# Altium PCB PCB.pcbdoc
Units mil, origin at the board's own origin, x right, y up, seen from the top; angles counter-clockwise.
Board outline 1334.95 x 2050.7 mil, 2 copper layers (Top Layer, Bottom Layer); 18 components, 22 nets, 95 pads, 86 vias.
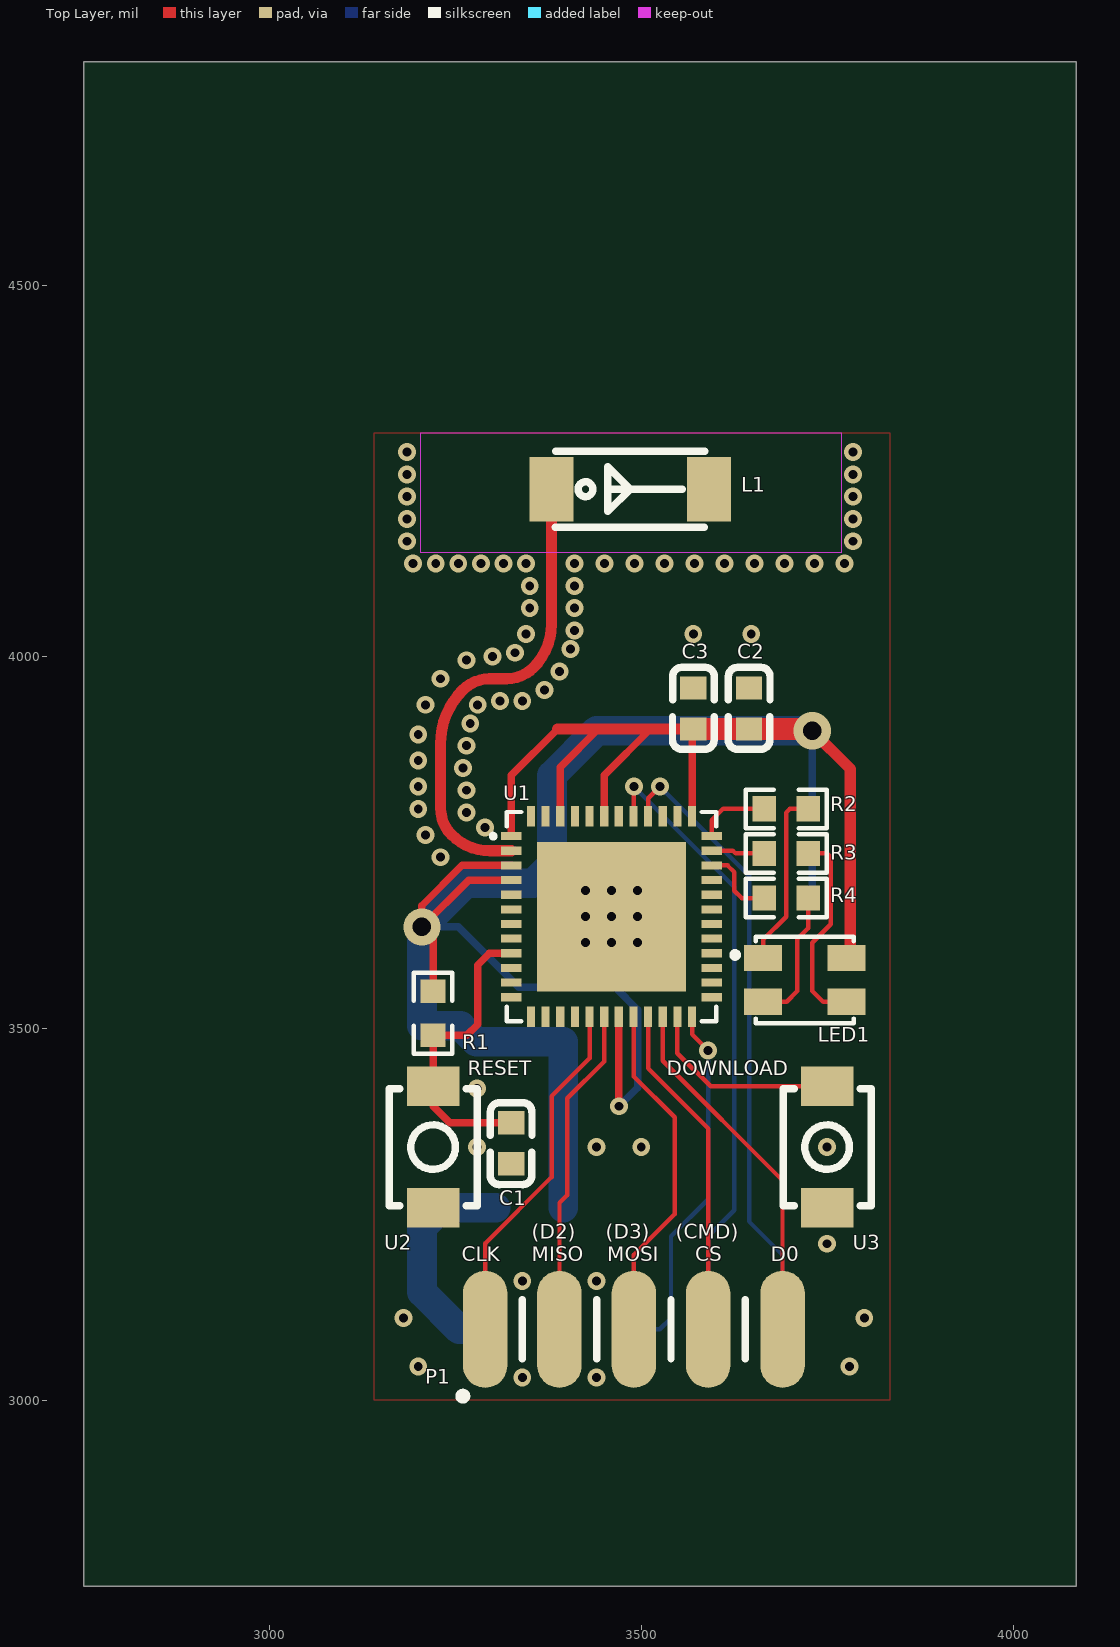
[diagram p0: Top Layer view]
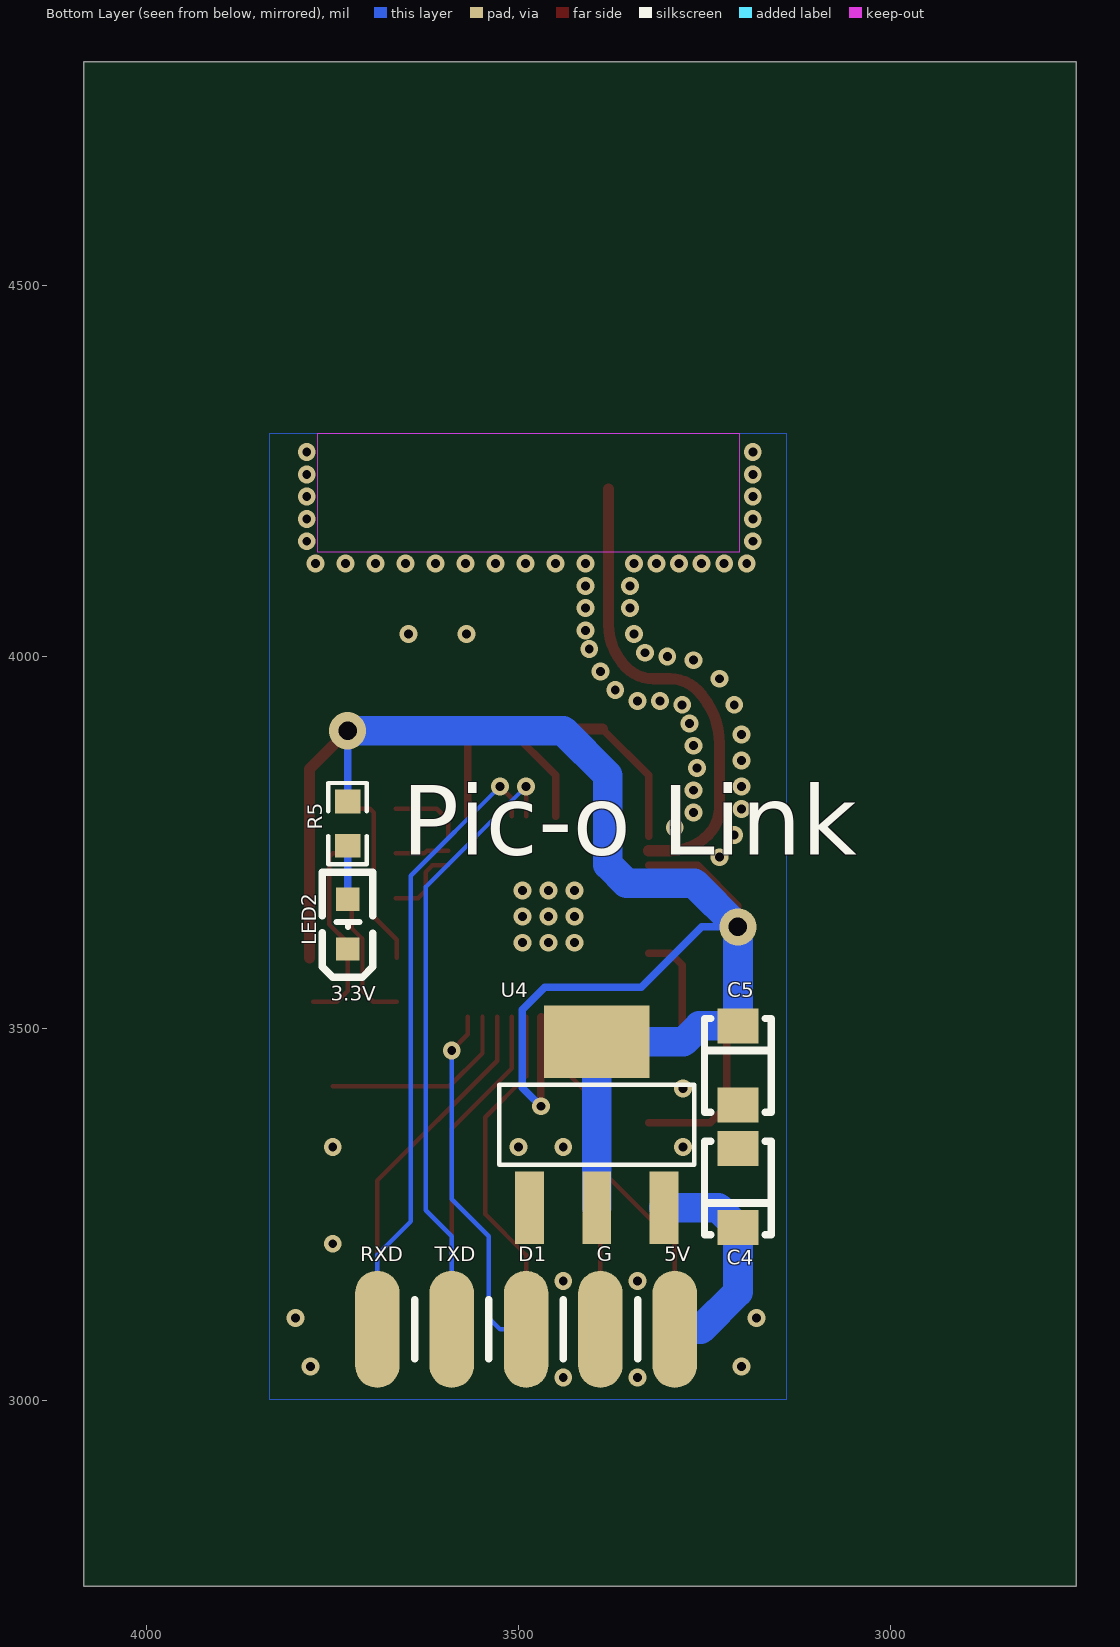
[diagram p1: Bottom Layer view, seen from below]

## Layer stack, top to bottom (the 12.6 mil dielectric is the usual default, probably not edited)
Top Solder: solder mask 0.4, Solder Resist, Dk 3.5
Top Layer: signal copper 1.4
Dielectric 1: dielectric 12.6, FR-4, Dk 4.8
Bottom Layer: signal copper 1.4
Bottom Solder: solder mask 0.4, Solder Resist, Dk 3.5

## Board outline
4084.95,2750 2750,2750 2750,4800.7 4084.95,4800.7

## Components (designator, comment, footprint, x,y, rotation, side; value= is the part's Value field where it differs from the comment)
C1 "" C0603_1 3324.95,3345.7 r90 top
C2 "" C0603_1 3644.95,3930.7 r270 top
C3 "" C0603_1 3569.95,3930.7 r270 top
C4 "" CAP-SMD_L3.2-W1.6 3204.95,3285.7 r90 bottom
C5 "" CAP-SMD_L3.2-W1.6 3204.95,3450.7 r270 bottom
L1 "" ANT2051_1 3484.95,4225.7 r0 top
LED1 "" LED-SMD_4P-L3.2-W2.7-TL_HL-AF-3528S39FU70GH20_1 3719.95,3565.7 r180 top
LED2 "" LED0603-R-RD 3729.95,3640.7 r90 bottom
P1 "" "2*5 双面 排针_2" 3489.95,3095.7 r90 top
R1 "" R0603_1 3219.95,3520.7 r90 top
R2 "" R0603_1 3694.95,3795.7 r180 top
R3 "" R0603_1 3694.95,3735.7 r180 top
R4 "" R0603_1 3694.95,3675.7 r180 top
R5 "" R0603_1 3729.95,3776 r90 bottom
U1 "" QFN-48_L7.0-W7.0-P0.50-BL-EP5.1 3459.95,3650.7 r270 top
U2 "" SW-SMD_L4.0-W3.0-LS4.8-1 3219.95,3340.7 r90 top
U3 "" SW-SMD_L4.0-W3.0-LS4.8-1 3749.95,3340.7 r90 top
U4 "" SOT-223-4_L6.5-W3.5-P2.30-LS7.0-BR_1 3394.95,3370.7 r270 bottom

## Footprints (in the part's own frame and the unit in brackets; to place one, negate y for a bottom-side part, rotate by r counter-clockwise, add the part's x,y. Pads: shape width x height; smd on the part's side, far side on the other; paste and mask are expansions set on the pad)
"2*5 双面 排针_2" [mm]
  oval 4x1.52 smd: 1(0,5.08) 3(0,2.54) 5(0,0) 7(0,-2.54) 9(0,-5.08)
  oval 4x1.52 smd far side: 2(0,5.08) 4(0,2.54) 6(0,0) 8(0,-2.54) 10(0,-5.08)
  silkscreen extent -2.41,-3.81 1.02,5.97
ANT2051_1 [mil]
  rect 59.1x86.6 smd: 1(-105.9,0) 2(105.9,0)
  silkscreen extent -101,-51 100,51
C0603_1 [mil]
  rect 31.5x35.4 smd: 1(-27.6,0) 2(27.6,0)
  silkscreen extent -55,-28 55,28
CAP-SMD_L3.2-W1.6 [mil]
  rect 47.2x55.1 smd: 1(-53.1,0) 2(53.2,0)
  silkscreen extent -63,-45 63,45
LED0603-R-RD [mm]
  rect 0.8x0.8 smd: 1(0.851,0) 2(-0.851,0)
  silkscreen extent -1.82,-0.86 1.77,0.86
LED-SMD_4P-L3.2-W2.7-TL_HL-AF-3528S39FU70GH20_1 [mil]
  rect 51.4x35.4 smd: 1(56.2,-29.5) 2(-56.2,-29.5) 3(-56.2,29.5) 4(56.2,29.5)
  Mid-Layer 2 circle w2.4: c-47.3,-55.1 r1.2
  silkscreen extent -66,-58 98,58
QFN-48_L7.0-W7.0-P0.50-BL-EP5.1 [mil]
  rect 11x27.6 smd: 1(-108.3,-134.9) 2(-88.6,-134.9) 3(-68.9,-134.9) 4(-49.2,-134.9) 5(-29.5,-134.9) 6(-9.8,-134.9) 7(9.8,-134.9) 8(29.5,-134.9) 9(49.2,-134.9) 10(68.9,-134.9) 11(88.6,-134.9) 12(108.3,-134.9) 25(108.3,134.9) 26(88.6,134.9) 27(68.9,134.9) 28(49.2,134.9) 29(29.5,134.9) 30(9.8,134.9) 31(-9.8,134.9) 32(-29.5,134.9) 33(-49.2,134.9) 34(-68.9,134.9) 35(-88.6,134.9) 36(-108.3,134.9)
  rect 27.6x11 smd: 13(134.9,-108.3) 14(134.9,-88.6) 15(134.9,-68.9) 16(134.9,-49.2) 17(134.9,-29.5) 18(134.9,-9.8) 19(134.9,9.8) 20(134.9,29.5) 21(134.9,49.2) 22(134.9,68.9) 23(134.9,88.6) 24(134.9,108.3) 37(-134.9,108.3) 38(-134.9,88.6) 39(-134.9,68.9) 40(-134.9,49.2) 41(-134.9,29.5) 42(-134.9,9.8) 43(-134.9,-9.8) 44(-134.9,-29.5) 45(-134.9,-49.2) 46(-134.9,-68.9) 47(-134.9,-88.6) 48(-134.9,-108.3)
  rect 200.8x200.8 smd: 49(0,0)
  silkscreen extent -141,-162 141,141
R0603_1 [mil]
  rect 31.8x34 smd: 1(-29.7,0) 2(29.7,0)
  silkscreen extent -54,-26 54,26
SOT-223-4_L6.5-W3.5-P2.30-LS7.0-BR_1 [mil]
  rect 97.2x38.6 smd: 1(111.6,-90.5) 2(111.6,0) 3(111.6,90.6)
  rect 97.2x141.7 smd: 4(-111.6,0)
  silkscreen extent -54,-131 54,131
SW-SMD_L4.0-W3.0-LS4.8-1 [mil]
  rect 53.2x70.9 smd: 1(-81.7,0) 2(81.7,0)
  silkscreen extent -79,-59 79,59

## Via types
v1: diameter 24.02, hole 12.01, Top Layer to Bottom Layer, 54 vias
v2: diameter 24, hole 12, Top Layer to Bottom Layer, 30 vias
v3: diameter 50, hole 25, Top Layer to Bottom Layer, 2 vias

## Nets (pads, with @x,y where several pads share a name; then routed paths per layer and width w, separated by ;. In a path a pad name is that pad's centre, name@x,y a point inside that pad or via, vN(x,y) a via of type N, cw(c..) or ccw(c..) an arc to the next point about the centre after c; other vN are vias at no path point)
$1N205: L1.1 U1.2 | length 642.3
  Top Layer w15: U1.2 3296.61,3739.3 cw(c3296.61,3812.36) 3244.95,3760.7 cw(c3281.16,3796.91) 3229.95,3796.91 3229.95,3883.27 cw(c3332.38,3883.27) 3259.95,3955.7 cw(c3296.16,3919.49) 3296.16,3970.7 3318.74,3970.7 ccw(c3318.74,4021.91) 3354.95,3985.7 ccw(c3296.77,4043.88) 3379.05,4043.88 L1.1
$1N302: LED1.1 R2.1 | length 240.2
  Top Layer w6: LED1.1 3663.75,3619.5 3694.95,3650.7 3694.95,3790.7 3699.95,3795.7 R2.1
$1N303: LED1.3 R3.1 | length 274.9
  Top Layer w6: R3.1 3749.95,3735.7 3754.95,3730.7 3754.95,3640.7 3729.95,3615.7 3729.95,3550.7 3744.45,3536.2 LED1.3
$1N304: LED1.4 R4.1 | length 183.3
  Top Layer w6: LED1.4 3695.45,3536.2 3709.95,3550.7 3709.95,3620.7 3724.65,3635.4 R4.1
$1N6027: U1.23 U3.2 | length 268.6
  Top Layer w6: U1.23 3548.55,3467.1 3593.25,3422.4 U3.2
$1N9569: LED2.1 R5.1 | length 72.1
  Bottom Layer w10: LED2.1 R5.1
B: R3.2 U1.35 | length 71.9
  Top Layer w6: U1.35 3623.24,3739.3 3626.84,3735.7 R3.2
CLK: P1.1 U1.17 | length 478.3
  Top Layer w6: P1.1 3289.95,3211.16 3379.24,3300.45 3379.24,3409.14 3430.45,3460.34 U1.17
CS: P1.7 U1.21 | length 453.6
  Top Layer w6: U1.21 3509.15,3446.5 3589.95,3365.7 P1.7
EN: C1.2 R1.1 U1.9 U2.2 | length 407.3
  Top Layer w10: C1.2 3242.35,3373.3 3219.95,3395.7 U2.2 R1.1 3265.25,3491 3279.95,3505.7 3279.95,3585.7 3295.75,3601.5 U1.9
G: R4.2 U1.34 | length 103.2
  Top Layer w6: U1.34 3616.05,3719.6 3624.95,3710.7 3624.95,3685.7 3634.95,3675.7 R4.2
GND: C1.1 C2.1 C3.1 C4.2 C5.2 LED2.2 P1.4 U1.49 U2.1 U3.1 U4.1
  other v1: 3199.95,3045.7 3779.95,3045.7 3179.95,3110.7 3799.95,3110.7 3749.95,3210.7 3279.05,3340.7 3439.95,3340.7 3499.95,3340.7 3749.95,3340.7 3279.05,3419.4 3424.95,3615.7 3459.95,3615.7 3494.95,3615.7 3424.95,3650.7 3459.95,3650.7 3494.95,3650.7 3424.95,3685.7 3459.95,3685.7 3494.95,3685.7 3229.95,3730.7 3209.95,3760.7 3289.95,3770.7 3264.95,3790.7 3199.95,3795.7 3264.95,3820.7 3199.95,3825.7 3259.95,3850.7 3199.95,3860.7 3264.95,3880.7 3199.95,3895.7 3269.95,3910.7 3209.95,3935.7 3279.95,3935.7 3309.95,3940.7 3339.95,3940.7 3369.95,3955.7 3229.95,3970.7 3389.95,3980.7 3264.95,3995.7 3299.95,4000.7 3329.95,4005.7 3404.95,4010.7 3344.95,4030.7 3569.95,4030.7 3647.88,4030.7 3409.95,4035.7 3349.95,4065.7 3409.95,4065.7 3349.95,4095.7 3409.95,4095.7
  other v2: 3339.95,3030.81 3439.95,3030.81 3339.95,3160.7 3439.95,3160.7 3193.1,4125.7 3223.47,4125.7 3253.84,4125.7 3284.21,4125.7 3314.58,4125.7 3344.95,4125.7 3409.95,4125.7 3450.32,4125.7 3490.68,4125.7 3531.05,4125.7 3571.42,4125.7 3611.78,4125.7 3652.15,4125.7 3692.51,4125.7 3732.88,4125.7 3773.25,4125.7 3184.95,4155.7 3784.95,4155.7 3184.95,4185.7 3784.95,4185.7 3184.95,4215.7 3784.95,4215.7 3184.95,4245.7 3784.95,4245.7 3184.95,4275.7 3784.95,4275.7
HS2_DATA0: P1.9 U1.22 | length 486.8
  Top Layer w6: U1.22 3528.85,3456.8 3689.95,3295.7 P1.9
HS2_DATA1: P1.6 U1.24 | length 491
  Top Layer w6: U1.24 3568.25,3492.4 v1(3589.95,3470.7)
  Bottom Layer w6: P1.6 3524.95,3095.7 3539.95,3110.7 3539.95,3220.7 3589.95,3270.7 v1(3589.95,3470.7)
MISO: P1.3 U1.18 | length 445
  Top Layer w6: P1.3 3389.95,3265.7 3400.5,3276.25 3400.5,3406.25 3450.15,3455.9 U1.18
MOSI: P1.5 U1.20 | length 465.9
  Top Layer w6: U1.20 3489.95,3515.3 3489.95,3435.7 3544.95,3380.7 3544.95,3250.7 3489.95,3195.7 P1.5
R: R2.2 U1.36 | length 98.3
  Top Layer w6: U1.36 3594.85,3780.6 3609.95,3795.7 R2.2
U0RXD: P1.10 U1.40 | length 845
  Top Layer w6: U1.40 3509.15,3809.9 v1(3524.95,3825.7)
  Bottom Layer w6: v1(3524.95,3825.7) 3644.95,3705.7 3644.95,3240.7 3689.95,3195.7 P1.10
U0TXD: P1.8 U1.41 | length 840.7
  Top Layer w6: U1.41 3489.95,3786.1 v1(3489.95,3825.7)
  Bottom Layer w6: v1(3489.95,3825.7) 3624.95,3690.7 3624.95,3255.7 3589.95,3220.7 P1.8
VCC_3V3: C2.2 C3.2 C5.1 LED1.2 R1.2 R5.2 U1.1 U1.3 U1.4 U1.19 U1.37 U1.43 U1.46 U4.2 U4.4 | length 3602
  Top Layer w10: R1.2 3219.95,3621.97 v3(3204.95,3636.97) ; U1.4 3267.88,3699.9 v3(3204.95,3636.97) ; U1.3 3258.85,3719.6 3204.95,3665.7 v3(3204.95,3636.97) ; U1.1 3325.05,3840.8 3387.35,3903.1 ; U1.46 3391.05,3851.8 3442.35,3903.1 ; U1.43 3450.15,3840.9 3512.35,3903.1 ; U1.19 3469.95,3515.6 v1(3469.95,3395.7) ; U1.37 3568.25,3901.4 C3.2
  Top Layer w15: 3387.35,3903.1 3442.35,3903.1 3512.35,3903.1 C3.2 ; v3(3729.95,3900.7) 3781.15,3849.5 LED1.2@3781.15,3595.2
  Top Layer w30: C3.2 C2.2 3727.55,3903.1 v3(3729.95,3900.7)
  Bottom Layer w10: v3(3204.95,3636.97) 3253.68,3636.97 3334.95,3555.7 3464.95,3555.7 3494.95,3525.7 3494.95,3420.7 v1(3469.95,3395.7) ; R5.2 v3(3729.95,3900.7)
  Bottom Layer w40: U4.2 U4.4 3278.35,3482.3 3256.85,3503.8 C5.1 v3(3204.95,3636.97) 3263.68,3695.7 3354.95,3695.7 3379.95,3720.7 3379.95,3840.7 3439.95,3900.7 v3(3729.95,3900.7)
VCC_5V: C4.1 P1.2 U4.3 | length 303
  Bottom Layer w40: P1.2 3254.95,3095.7 3204.95,3145.7 C4.1 3231.45,3259.1 U4.3
"": L1.2 U1.5 U1.6 U1.7 U1.8 U1.10 U1.11 U1.12 U1.13 U1.14 U1.15 U1.16 U1.25 U1.26 U1.27 U1.28 U1.29 U1.30 U1.31 U1.32 U1.33 U1.38 U1.39 U1.42 U1.44 U1.45 U1.47 U1.48

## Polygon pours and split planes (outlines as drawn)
GND on Top Layer (solid, remove dead copper, pour order 0): 3139.95,3000.7 3834.95,3000.7 3834.95,4300.7 3139.95,4300.7
GND on Bottom Layer (solid, remove dead copper, pour order 1): 3139.95,3000.7 3834.95,3000.7 3834.95,4300.7 3139.95,4300.7

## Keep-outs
Top Layer:
  region net "": 3202.95,4140.7 3769.95,4140.7 3769.95,4300.7 3202.95,4300.7
Bottom Layer:
  region net "": 3202.95,4140.7 3769.95,4140.7 3769.95,4300.7 3202.95,4300.7

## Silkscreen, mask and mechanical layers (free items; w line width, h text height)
Top Overlay:
  text "RESET" at 3266.58,3437.36 h19.47
  text "DOWNLOAD" at 3534.01,3437.36 h19.47
  text "(D2)" at 3352.43,3217.28 h19.47
  text "(D3)" at 3452.43,3217.28 h19.47
  text "(CMD)" at 3546.58,3217.28 h19.47
  text "CLK" at 3258.29,3187.36 h19.47
  text "MISO" at 3352.88,3187.36 h19.47
  text "MOSI" at 3454.33,3187.36 h19.47
  text "CS" at 3572.29,3187.36 h19.47
  text "D0" at 3674.14,3187.36 h19.47
Bottom Overlay:
  text "Pic-o Link" at 3656.86,3733.86 h93.59
  text "3.3V" at 3752.43,3537.36 h19.47
  text "5V" at 3304.14,3187.36 h19.47
  text "G" at 3395.2,3187.29 h19.61
  text "D1" at 3500.24,3187.36 h19.47
  text "TXD" at 3612.99,3187.36 h19.47
  text "RXD" at 3713.29,3187.36 h19.47
Top Solder:
  region net "": 3202.95,4140.7 3769.95,4140.7 3769.95,4300.7 3202.95,4300.7
Bottom Solder:
  region net "": 3202.95,4140.7 3769.95,4140.7 3769.95,4300.7 3202.95,4300.7
Mechanical 1:
  lines w10 net "": 3139.95,3060.54 3139.95,4237.71 cw(c3200.44,4240.21) 3202.94,4300.7 3769.87,4300.7 cw(c3772.37,4240.21) 3832.86,4237.71 3139.95,3060.54 ; 3140,3063.04 ccw(c3200.49,3060.54) 3202.99,3000.05 3769.92,3000.05 ccw(c3772.43,3060.54) 3832.92,3063.04 3832.92,4240.21 3140,3063.04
